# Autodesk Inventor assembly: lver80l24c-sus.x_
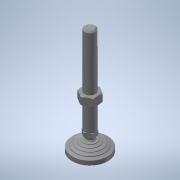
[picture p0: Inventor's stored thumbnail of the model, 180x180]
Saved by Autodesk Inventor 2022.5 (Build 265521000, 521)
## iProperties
Part Number: lver80l24c-sus.x_
Material: 一般
Document SubType Name: Assembly
Designer: ImaoCorp
Sending System: SOLIDWORKS 2017-2017317
MC: AMD64
MC_MODEL: Intel64 Family 6 Model 60 Stepping 3, GenuineIntel
OS: Windows_NT
FRU: Parasolid Version 29.0, build 201,  4-17-2017
FORMAT: text
GUISE: transmit
KEY: lver80l24c-sus
FILE: lver80l24c-sus.x_t
DATE: Mon Jul 01 18:27:58 2019
Author: ImaoCorp
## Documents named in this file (3)
- X:\14_SW2022-Inv2022\00_全2023-1023新製品(TCC)まで\l\lver80l24c-sus\LVER80L24C-SUS.iam
- X:\14_SW2022-Inv2022\00_全2023-1023新製品(TCC)まで\l\lver80l24c-sus\lver80l24c-sus_01.ipt
- X:\14_SW2022-Inv2022\00_全2023-1023新製品(TCC)まで\l\lver80l24c-sus\lver80l24c-sus_02.ipt
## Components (2 placed, 2 different names)
1. lver80l24c-sus_01
2. lver80l24c-sus_02
